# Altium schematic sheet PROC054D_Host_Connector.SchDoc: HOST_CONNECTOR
size 558 x 431 mm; Date: Not shown in title block; ApprovedBy: Not shown in title block; CheckedBy: Not shown in title block; Author: Not shown in title block; CompanyName: Not shown in title block; DrawnBy: a0271760; Engineer: Not shown in title block; Organization: Not shown in title block; Address1: Not shown in title block; Address2: Not shown in title block; Address3: Not shown in title block; Address4: Not shown in title block; DocumentNumber: 9; Revision: Use project pAWRameter SCH_Rev; SheetNumber: 9; SheetTotal: 19; PageSetup: Record=PageOptions¦CenterHorizontal=True¦CenterVertical=True¦PrintScale=1.00¦XCorrection=1.00¦YCorrection=1.00¦PrintKind=0¦BorderSize=5000000¦LeftOffset=0¦BottomOffset=0¦Orientation=2¦PaperLength=1000¦PaperWidth=1000¦Scale=100¦PaperSource=15¦PrintQuality=600¦MediaType=1¦DitherType=10¦PaperKind=Letter¦PrintScaleMode=1
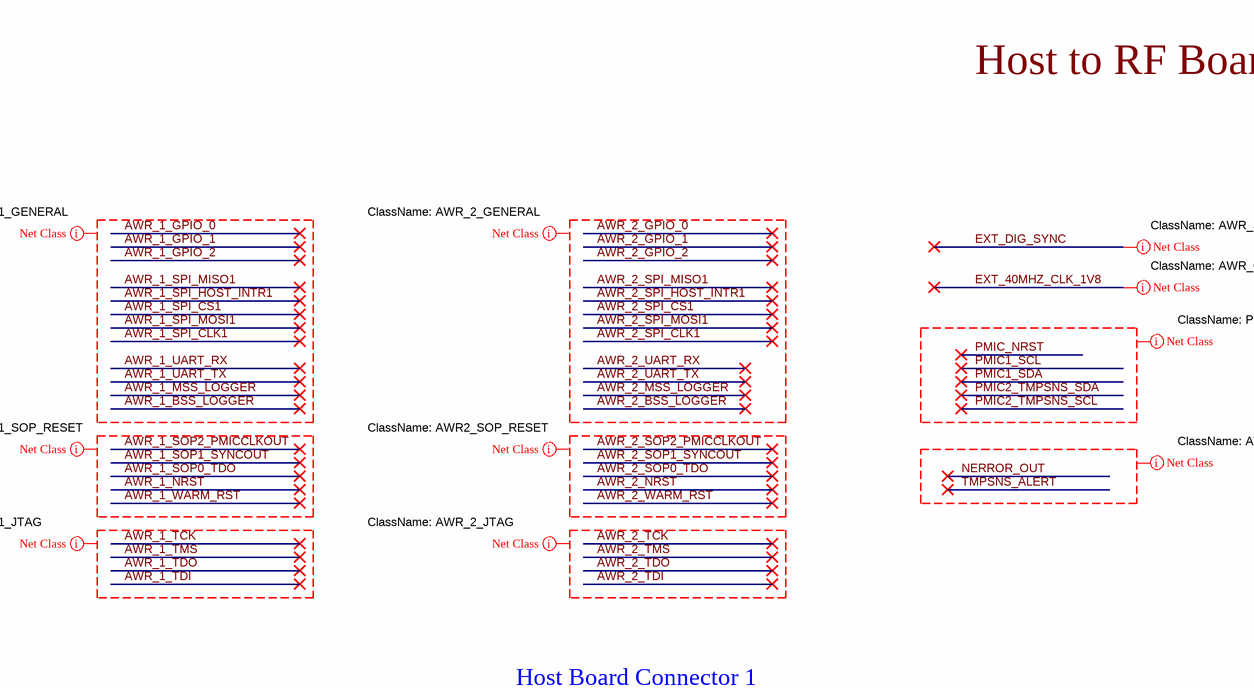
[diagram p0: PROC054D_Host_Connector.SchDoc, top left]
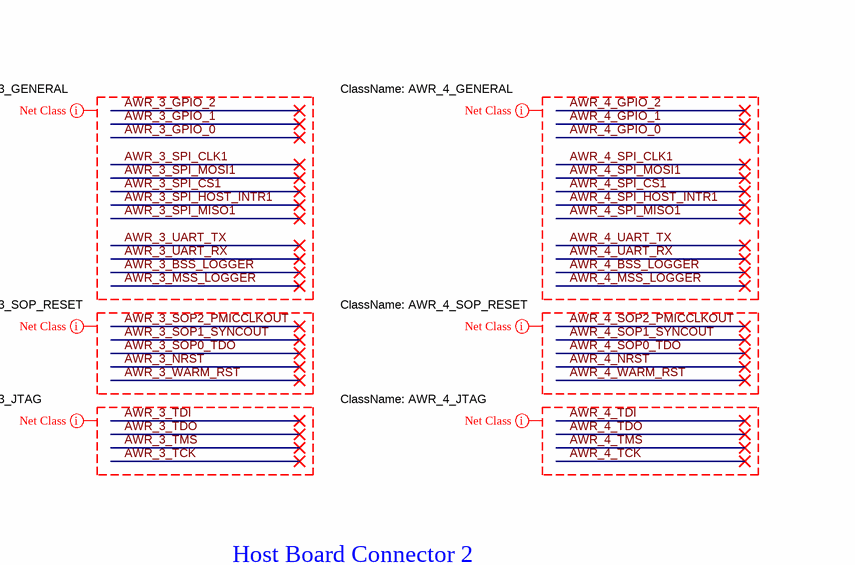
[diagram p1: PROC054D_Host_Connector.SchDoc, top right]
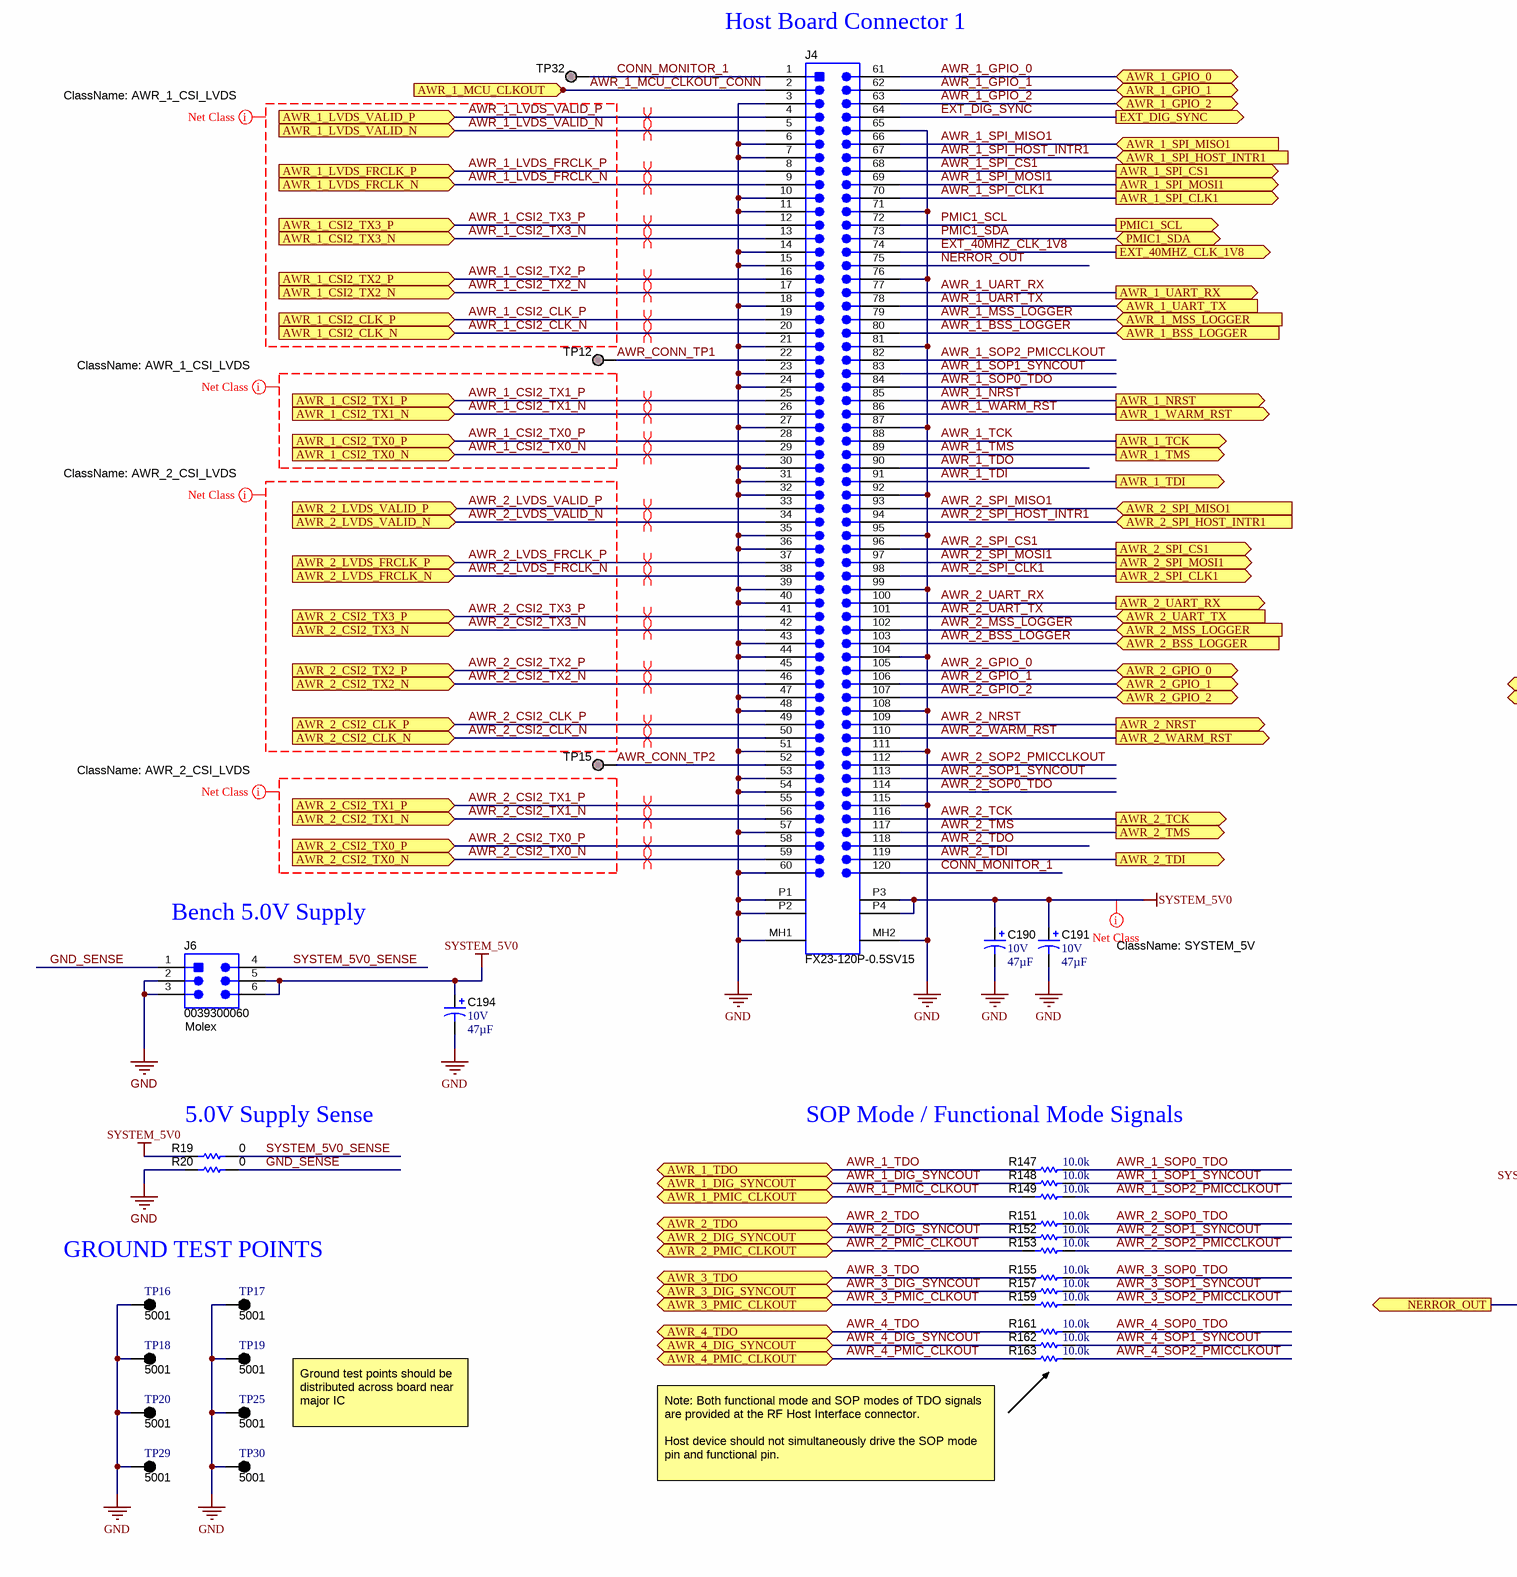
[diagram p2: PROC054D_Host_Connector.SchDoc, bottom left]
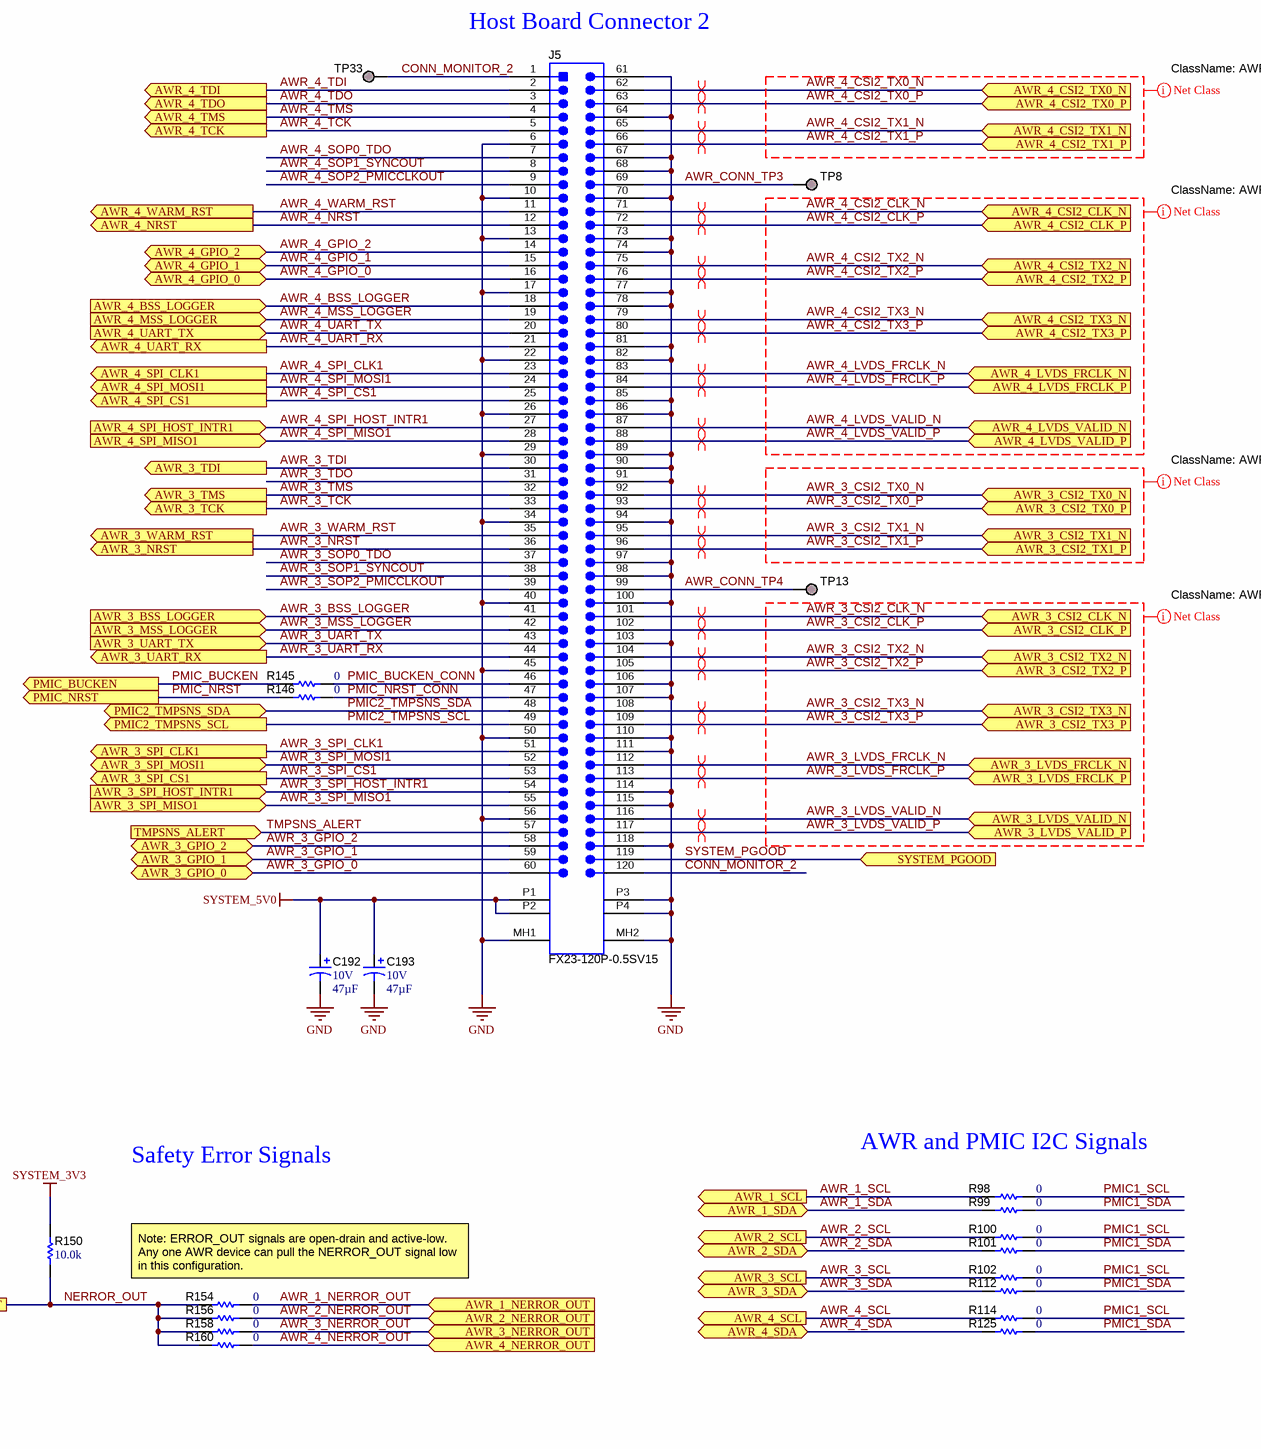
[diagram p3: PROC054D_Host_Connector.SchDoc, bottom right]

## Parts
C190  VDC_V: 10V  ValueDisplayed: 47µF  [3528-21]  (hidden comment: T491B476K010AT)
C191  VDC_V: 10V  ValueDisplayed: 47µF  [3528-21]  (hidden comment: T491B476K010AT)
C192  VDC_V: 10V  ValueDisplayed: 47µF  [3528-21]  (hidden comment: T491B476K010AT)
C193  VDC_V: 10V  ValueDisplayed: 47µF  [3528-21]  (hidden comment: T491B476K010AT)
C194  VDC_V: 10V  ValueDisplayed: 47µF  [3528-21]  (hidden comment: T491B476K010AT)
J4  FX23-120P-0.5SV15  [Hirose_FX23-120P-0_5SV15]
J5  FX23-120P-0.5SV15  [Hirose_FX23-120P-0_5SV15]
J6  0039300060  Manufacturer: Molex  [Molex_0039300060]
R19  ValueDisplayed: 0  [0805L]  (hidden comment: PMR10EZPJ000)
R20  ValueDisplayed: 0  [0805L]  (hidden comment: PMR10EZPJ000)
R98  ValueDisplayed: 0  [0402S]  (hidden comment: CRCW04020000Z0EDHP)
R99  ValueDisplayed: 0  [0402S]  (hidden comment: CRCW04020000Z0EDHP)
R100  ValueDisplayed: 0  [0402S]  (hidden comment: CRCW04020000Z0EDHP)
R101  ValueDisplayed: 0  [0402S]  (hidden comment: CRCW04020000Z0EDHP)
R102  ValueDisplayed: 0  [0402S]  (hidden comment: CRCW04020000Z0EDHP)
R112  ValueDisplayed: 0  [0402S]  (hidden comment: CRCW04020000Z0EDHP)
R114  ValueDisplayed: 0  [0402S]  (hidden comment: CRCW04020000Z0EDHP)
R125  ValueDisplayed: 0  [0402S]  (hidden comment: CRCW04020000Z0EDHP)
R145  ValueDisplayed: 0  [0402]  (hidden comment: ERJ-2GE0R00X)
R146  ValueDisplayed: 0  [0402]  (hidden comment: ERJ-2GE0R00X)
R147  ValueDisplayed: 10.0k  [0402]  (hidden comment: CRCW040210K0FKED)
R148  ValueDisplayed: 10.0k  [0402]  (hidden comment: CRCW040210K0FKED)
R149  ValueDisplayed: 10.0k  [0402]  (hidden comment: CRCW040210K0FKED)
R150  ValueDisplayed: 10.0k  [0402]  (hidden comment: CRCW040210K0FKED)
R151  ValueDisplayed: 10.0k  [0402]  (hidden comment: CRCW040210K0FKED)
R152  ValueDisplayed: 10.0k  [0402]  (hidden comment: CRCW040210K0FKED)
R153  ValueDisplayed: 10.0k  [0402]  (hidden comment: CRCW040210K0FKED)
R154  ValueDisplayed: 0  [0402S]  (hidden comment: CRCW04020000Z0EDHP)
R155  ValueDisplayed: 10.0k  [0402]  (hidden comment: CRCW040210K0FKED)
R156  ValueDisplayed: 0  [0402S]  (hidden comment: CRCW04020000Z0EDHP)
R157  ValueDisplayed: 10.0k  [0402]  (hidden comment: CRCW040210K0FKED)
R158  ValueDisplayed: 0  [0402S]  (hidden comment: CRCW04020000Z0EDHP)
R159  ValueDisplayed: 10.0k  [0402]  (hidden comment: CRCW040210K0FKED)
R160  ValueDisplayed: 0  [0402S]  (hidden comment: CRCW04020000Z0EDHP)
R161  ValueDisplayed: 10.0k  [0402]  (hidden comment: CRCW040210K0FKED)
R162  ValueDisplayed: 10.0k  [0402]  (hidden comment: CRCW040210K0FKED)
R163  ValueDisplayed: 10.0k  [0402]  (hidden comment: CRCW040210K0FKED)
TP8  TP_SM_1MM  [TP_SM_1MM]  (value not drawn)  (no BOM)
TP12  TP_SM_1MM  [TP_SM_1MM]  (value not drawn)  (no BOM)
TP13  TP_SM_1MM  [TP_SM_1MM]  (value not drawn)  (no BOM)
TP15  TP_SM_1MM  [TP_SM_1MM]  (value not drawn)  (no BOM)
TP16  5001  [Keystone5001]
TP17  5001  [Keystone5001]
TP18  5001  [Keystone5001]
TP19  5001  [Keystone5001]
TP20  5001  [Keystone5001]
TP25  5001  [Keystone5001]
TP29  5001  [Keystone5001]
TP30  5001  [Keystone5001]
TP32  TP_SM_1MM  [TP_SM_1MM]  (value not drawn)  (no BOM)
TP33  TP_SM_1MM  [TP_SM_1MM]  (value not drawn)  (no BOM)

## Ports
AWR_1_BSS_LOGGER (in), AWR_1_CSI2_CLK_N (in), AWR_1_CSI2_CLK_P (in), AWR_1_CSI2_TX0_N (in), AWR_1_CSI2_TX0_P (in), AWR_1_CSI2_TX1_N (in), AWR_1_CSI2_TX1_P (in), AWR_1_CSI2_TX2_N (in), AWR_1_CSI2_TX2_P (in), AWR_1_CSI2_TX3_N (in), AWR_1_CSI2_TX3_P (in), AWR_1_DIG_SYNCOUT (bidir), AWR_1_GPIO_0 (bidir), AWR_1_GPIO_1 (bidir), AWR_1_GPIO_2 (bidir), AWR_1_LVDS_FRCLK_N (in), AWR_1_LVDS_FRCLK_P (in), AWR_1_LVDS_VALID_N (in), AWR_1_LVDS_VALID_P (in), AWR_1_MCU_CLKOUT (in), AWR_1_MSS_LOGGER (in), AWR_1_NERROR_OUT (in), AWR_1_NRST (out), AWR_1_PMIC_CLKOUT (bidir), AWR_1_SCL (out), AWR_1_SDA (bidir), AWR_1_SPI_CLK1 (out), AWR_1_SPI_CS1 (out), AWR_1_SPI_HOST_INTR1 (in), AWR_1_SPI_MISO1 (in), AWR_1_SPI_MOSI1 (out), AWR_1_TCK (out), AWR_1_TDI (out), AWR_1_TDO (bidir), AWR_1_TMS (out), AWR_1_UART_RX (out), AWR_1_UART_TX (in), AWR_1_WARM_RST (out), AWR_2_BSS_LOGGER (in), AWR_2_CSI2_CLK_N (in), AWR_2_CSI2_CLK_P (in), AWR_2_CSI2_TX0_N (in), AWR_2_CSI2_TX0_P (in), AWR_2_CSI2_TX1_N (in), AWR_2_CSI2_TX1_P (in), AWR_2_CSI2_TX2_N (in), AWR_2_CSI2_TX2_P (in), AWR_2_CSI2_TX3_N (in), AWR_2_CSI2_TX3_P (in), AWR_2_DIG_SYNCOUT (bidir), AWR_2_GPIO_0 (bidir), AWR_2_GPIO_1 (bidir), AWR_2_GPIO_2 (bidir), AWR_2_LVDS_FRCLK_N (in), AWR_2_LVDS_FRCLK_P (in), AWR_2_LVDS_VALID_N (in), AWR_2_LVDS_VALID_P (in), AWR_2_MSS_LOGGER (in), AWR_2_NERROR_OUT (in), AWR_2_NRST (out), AWR_2_PMIC_CLKOUT (bidir), AWR_2_SCL (out), AWR_2_SDA (bidir), AWR_2_SPI_CLK1 (out), AWR_2_SPI_CS1 (out), AWR_2_SPI_HOST_INTR1 (in), AWR_2_SPI_MISO1 (in), AWR_2_SPI_MOSI1 (out), AWR_2_TCK (out), AWR_2_TDI (out), AWR_2_TDO (bidir), AWR_2_TMS (out), AWR_2_UART_RX (out), AWR_2_UART_TX (in), AWR_2_WARM_RST (out), AWR_3_BSS_LOGGER (in), AWR_3_CSI2_CLK_N (in), AWR_3_CSI2_CLK_P (in), AWR_3_CSI2_TX0_N (in), AWR_3_CSI2_TX0_P (in), AWR_3_CSI2_TX1_N (in), AWR_3_CSI2_TX1_P (in), AWR_3_CSI2_TX2_N (in), AWR_3_CSI2_TX2_P (in), AWR_3_CSI2_TX3_N (in), AWR_3_CSI2_TX3_P (in), AWR_3_DIG_SYNCOUT (bidir), AWR_3_GPIO_0 (bidir), AWR_3_GPIO_1 (bidir), AWR_3_GPIO_2 (bidir), AWR_3_LVDS_FRCLK_N (in), AWR_3_LVDS_FRCLK_P (in), AWR_3_LVDS_VALID_N (in), AWR_3_LVDS_VALID_P (in), AWR_3_MSS_LOGGER (in), AWR_3_NERROR_OUT (in), AWR_3_NRST (out), AWR_3_PMIC_CLKOUT (bidir), AWR_3_SCL (out), AWR_3_SDA (bidir), AWR_3_SPI_CLK1 (out), AWR_3_SPI_CS1 (out), AWR_3_SPI_HOST_INTR1 (in), AWR_3_SPI_MISO1 (in), AWR_3_SPI_MOSI1 (bidir), AWR_3_TCK (out), AWR_3_TDI (out), AWR_3_TDO (bidir), AWR_3_TMS (out), AWR_3_UART_RX (out), AWR_3_UART_TX (in), AWR_3_WARM_RST (out), AWR_4_BSS_LOGGER (in), AWR_4_CSI2_CLK_N (in), AWR_4_CSI2_CLK_P (in), AWR_4_CSI2_TX0_N (in), AWR_4_CSI2_TX0_P (in), AWR_4_CSI2_TX1_N (in), AWR_4_CSI2_TX1_P (in), AWR_4_CSI2_TX2_N (in), AWR_4_CSI2_TX2_P (in), AWR_4_CSI2_TX3_N (in), AWR_4_CSI2_TX3_P (in), AWR_4_DIG_SYNCOUT (bidir), AWR_4_GPIO_0 (bidir), AWR_4_GPIO_1 (bidir), AWR_4_GPIO_2 (bidir), AWR_4_LVDS_FRCLK_N (in), AWR_4_LVDS_FRCLK_P (in), AWR_4_LVDS_VALID_N (in), AWR_4_LVDS_VALID_P (in), AWR_4_MSS_LOGGER (in), AWR_4_NERROR_OUT (in), AWR_4_NRST (out), AWR_4_PMIC_CLKOUT (bidir), AWR_4_SCL (out), AWR_4_SDA (bidir), AWR_4_SPI_CLK1 (out), AWR_4_SPI_CS1 (out), AWR_4_SPI_HOST_INTR1 (in), AWR_4_SPI_MISO1 (in), AWR_4_SPI_MOSI1 (out), AWR_4_TCK (out), AWR_4_TDI (out), AWR_4_TDO (bidir), AWR_4_TDO (out), AWR_4_TMS (out), AWR_4_UART_RX (out), AWR_4_UART_TX (in), AWR_4_WARM_RST (out), EXT_40MHZ_CLK_1V8 (out), EXT_DIG_SYNC (out), NERROR_OUT (out), PMIC1_SCL (out), PMIC1_SDA (bidir), PMIC2_TMPSNS_SCL (out), PMIC2_TMPSNS_SDA (bidir), PMIC_BUCKEN (out), PMIC_NRST (out), SYSTEM_PGOOD (in), TMPSNS_ALERT (in)

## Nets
GND: C190.2(-) C191.2(-) C192.2(-) C193.2(-) C194.2(-) J4.3 J4.6 J4.7 J4.10 J4.11 J4.14 J4.15 J4.18 J4.21 J4.23 J4.24 J4.27 J4.30 J4.31 J4.32 J4.35 J4.36 J4.39 J4.40 J4.43 J4.44 J4.47 J4.48 J4.51 J4.53 J4.54 J4.57 J4.60 J4.65 J4.71 J4.76 J4.81 J4.87 J4.92 J4.95 J4.99 J4.104 J4.108 J4.111 J4.115 J4.MH1 J4.MH2 J4.P1 J4.P2 J5.6 J5.10 J5.13 J5.17 J5.22 J5.26 J5.29 J5.34 J5.40 J5.45 J5.50 J5.56 J5.61 J5.64 J5.67 J5.68 J5.70 J5.73 J5.74 J5.77 J5.78 J5.81 J5.82 J5.85 J5.86 J5.89 J5.90 J5.91 J5.94 J5.97 J5.98 J5.100 J5.103 J5.106 J5.107 J5.110 J5.111 J5.114 J5.115 J5.118 J5.MH1 J5.MH2 J5.P3 J5.P4 J6.2 J6.3 R20.1 TP16.1 TP17.1 TP18.1 TP19.1 TP20.1 TP25.1 TP29.1 TP30.1
SYSTEM_3V3: R150.2
SYSTEM_5V0: C190.1(+) C191.1(+) C192.1(+) C193.1(+) C194.1(+) J4.P3 J4.P4 J5.P1 J5.P2 J6.5 J6.6 R19.1
AWR_1_BSS_LOGGER: J4.80 ; port AWR_1_BSS_LOGGER
AWR_1_CSI2_CLK_N: J4.20 ; port AWR_1_CSI2_CLK_N
AWR_1_CSI2_CLK_P: J4.19 ; port AWR_1_CSI2_CLK_P
AWR_1_CSI2_TX0_N: J4.29 ; port AWR_1_CSI2_TX0_N
AWR_1_CSI2_TX0_P: J4.28 ; port AWR_1_CSI2_TX0_P
AWR_1_CSI2_TX1_N: J4.26 ; port AWR_1_CSI2_TX1_N
AWR_1_CSI2_TX1_P: J4.25 ; port AWR_1_CSI2_TX1_P
AWR_1_CSI2_TX2_N: J4.17 ; port AWR_1_CSI2_TX2_N
AWR_1_CSI2_TX2_P: J4.16 ; port AWR_1_CSI2_TX2_P
AWR_1_CSI2_TX3_N: J4.13 ; port AWR_1_CSI2_TX3_N
AWR_1_CSI2_TX3_P: J4.12 ; port AWR_1_CSI2_TX3_P
AWR_1_DIG_SYNCOUT: R148.1 ; port AWR_1_DIG_SYNCOUT
AWR_1_GPIO_0: J4.61 ; port AWR_1_GPIO_0
AWR_1_GPIO_1: J4.62 ; port AWR_1_GPIO_1
AWR_1_GPIO_2: J4.63 ; port AWR_1_GPIO_2
AWR_1_LVDS_FRCLK_N: J4.9 ; port AWR_1_LVDS_FRCLK_N
AWR_1_LVDS_FRCLK_P: J4.8 ; port AWR_1_LVDS_FRCLK_P
AWR_1_LVDS_VALID_N: J4.5 ; port AWR_1_LVDS_VALID_N
AWR_1_LVDS_VALID_P: J4.4 ; port AWR_1_LVDS_VALID_P
AWR_1_MCU_CLKOUT_CONN: J4.2 ; port AWR_1_MCU_CLKOUT
AWR_1_MSS_LOGGER: J4.79 ; port AWR_1_MSS_LOGGER
AWR_1_NERROR_OUT: R154.1 ; port AWR_1_NERROR_OUT
AWR_1_NRST: J4.85 ; port AWR_1_NRST
AWR_1_PMIC_CLKOUT: R149.1 ; port AWR_1_PMIC_CLKOUT
AWR_1_SCL: R98.2 ; port AWR_1_SCL
AWR_1_SDA: R99.2 ; port AWR_1_SDA
AWR_1_SOP0_TDO: J4.84 R147.2
AWR_1_SOP1_SYNCOUT: J4.83 R148.2
AWR_1_SOP2_PMICCLKOUT: J4.82 R149.2
AWR_1_SPI_CLK1: J4.70 ; port AWR_1_SPI_CLK1
AWR_1_SPI_CS1: J4.68 ; port AWR_1_SPI_CS1
AWR_1_SPI_HOST_INTR1: J4.67 ; port AWR_1_SPI_HOST_INTR1
AWR_1_SPI_MISO1: J4.66 ; port AWR_1_SPI_MISO1
AWR_1_SPI_MOSI1: J4.69 ; port AWR_1_SPI_MOSI1
AWR_1_TCK: J4.88 ; port AWR_1_TCK
AWR_1_TDI: J4.91 ; port AWR_1_TDI
AWR_1_TDO: J4.90 R147.1 ; port AWR_1_TDO
AWR_1_TMS: J4.89 ; port AWR_1_TMS
AWR_1_UART_RX: J4.77 ; port AWR_1_UART_RX
AWR_1_UART_TX: J4.78 ; port AWR_1_UART_TX
AWR_1_WARM_RST: J4.86 ; port AWR_1_WARM_RST
AWR_2_BSS_LOGGER: J4.103 ; port AWR_2_BSS_LOGGER
AWR_2_CSI2_CLK_N: J4.50 ; port AWR_2_CSI2_CLK_N
AWR_2_CSI2_CLK_P: J4.49 ; port AWR_2_CSI2_CLK_P
AWR_2_CSI2_TX0_N: J4.59 ; port AWR_2_CSI2_TX0_N
AWR_2_CSI2_TX0_P: J4.58 ; port AWR_2_CSI2_TX0_P
AWR_2_CSI2_TX1_N: J4.56 ; port AWR_2_CSI2_TX1_N
AWR_2_CSI2_TX1_P: J4.55 ; port AWR_2_CSI2_TX1_P
AWR_2_CSI2_TX2_N: J4.46 ; port AWR_2_CSI2_TX2_N
AWR_2_CSI2_TX2_P: J4.45 ; port AWR_2_CSI2_TX2_P
AWR_2_CSI2_TX3_N: J4.42 ; port AWR_2_CSI2_TX3_N
AWR_2_CSI2_TX3_P: J4.41 ; port AWR_2_CSI2_TX3_P
AWR_2_DIG_SYNCOUT: R152.1 ; port AWR_2_DIG_SYNCOUT
AWR_2_GPIO_0: J4.105 ; port AWR_2_GPIO_0
AWR_2_GPIO_1: J4.106 ; port AWR_2_GPIO_1
AWR_2_GPIO_2: J4.107 ; port AWR_2_GPIO_2
AWR_2_LVDS_FRCLK_N: J4.38 ; port AWR_2_LVDS_FRCLK_N
AWR_2_LVDS_FRCLK_P: J4.37 ; port AWR_2_LVDS_FRCLK_P
AWR_2_LVDS_VALID_N: J4.34 ; port AWR_2_LVDS_VALID_N
AWR_2_LVDS_VALID_P: J4.33 ; port AWR_2_LVDS_VALID_P
AWR_2_MSS_LOGGER: J4.102 ; port AWR_2_MSS_LOGGER
AWR_2_NERROR_OUT: R156.1 ; port AWR_2_NERROR_OUT
AWR_2_NRST: J4.109 ; port AWR_2_NRST
AWR_2_PMIC_CLKOUT: R153.1 ; port AWR_2_PMIC_CLKOUT
AWR_2_SCL: R100.2 ; port AWR_2_SCL
AWR_2_SDA: R101.2 ; port AWR_2_SDA
AWR_2_SOP0_TDO: J4.114 R151.2
AWR_2_SOP1_SYNCOUT: J4.113 R152.2
AWR_2_SOP2_PMICCLKOUT: J4.112 R153.2
AWR_2_SPI_CLK1: J4.98 ; port AWR_2_SPI_CLK1
AWR_2_SPI_CS1: J4.96 ; port AWR_2_SPI_CS1
AWR_2_SPI_HOST_INTR1: J4.94 ; port AWR_2_SPI_HOST_INTR1
AWR_2_SPI_MISO1: J4.93 ; port AWR_2_SPI_MISO1
AWR_2_SPI_MOSI1: J4.97 ; port AWR_2_SPI_MOSI1
AWR_2_TCK: J4.116 ; port AWR_2_TCK
AWR_2_TDI: J4.119 ; port AWR_2_TDI
AWR_2_TDO: J4.118 R151.1 ; port AWR_2_TDO
AWR_2_TMS: J4.117 ; port AWR_2_TMS
AWR_2_UART_RX: J4.100 ; port AWR_2_UART_RX
AWR_2_UART_TX: J4.101 ; port AWR_2_UART_TX
AWR_2_WARM_RST: J4.110 ; port AWR_2_WARM_RST
AWR_3_BSS_LOGGER: J5.41 ; port AWR_3_BSS_LOGGER
AWR_3_CSI2_CLK_N: J5.101 ; port AWR_3_CSI2_CLK_N
AWR_3_CSI2_CLK_P: J5.102 ; port AWR_3_CSI2_CLK_P
AWR_3_CSI2_TX0_N: J5.92 ; port AWR_3_CSI2_TX0_N
AWR_3_CSI2_TX0_P: J5.93 ; port AWR_3_CSI2_TX0_P
AWR_3_CSI2_TX1_N: J5.95 ; port AWR_3_CSI2_TX1_N
AWR_3_CSI2_TX1_P: J5.96 ; port AWR_3_CSI2_TX1_P
AWR_3_CSI2_TX2_N: J5.104 ; port AWR_3_CSI2_TX2_N
AWR_3_CSI2_TX2_P: J5.105 ; port AWR_3_CSI2_TX2_P
AWR_3_CSI2_TX3_N: J5.108 ; port AWR_3_CSI2_TX3_N
AWR_3_CSI2_TX3_P: J5.109 ; port AWR_3_CSI2_TX3_P
AWR_3_DIG_SYNCOUT: R157.1 ; port AWR_3_DIG_SYNCOUT
AWR_3_GPIO_0: J5.60 ; port AWR_3_GPIO_0
AWR_3_GPIO_1: J5.59 ; port AWR_3_GPIO_1
AWR_3_GPIO_2: J5.58 ; port AWR_3_GPIO_2
AWR_3_LVDS_FRCLK_N: J5.112 ; port AWR_3_LVDS_FRCLK_N
AWR_3_LVDS_FRCLK_P: J5.113 ; port AWR_3_LVDS_FRCLK_P
AWR_3_LVDS_VALID_N: J5.116 ; port AWR_3_LVDS_VALID_N
AWR_3_LVDS_VALID_P: J5.117 ; port AWR_3_LVDS_VALID_P
AWR_3_MSS_LOGGER: J5.42 ; port AWR_3_MSS_LOGGER
AWR_3_NERROR_OUT: R158.1 ; port AWR_3_NERROR_OUT
AWR_3_NRST: J5.36 ; port AWR_3_NRST
AWR_3_PMIC_CLKOUT: R159.1 ; port AWR_3_PMIC_CLKOUT
AWR_3_SCL: R102.2 ; port AWR_3_SCL
AWR_3_SDA: R112.2 ; port AWR_3_SDA
AWR_3_SOP0_TDO: J5.37 R155.2
AWR_3_SOP1_SYNCOUT: J5.38 R157.2
AWR_3_SOP2_PMICCLKOUT: J5.39 R159.2
AWR_3_SPI_CLK1: J5.51 ; port AWR_3_SPI_CLK1
AWR_3_SPI_CS1: J5.53 ; port AWR_3_SPI_CS1
AWR_3_SPI_HOST_INTR1: J5.54 ; port AWR_3_SPI_HOST_INTR1
AWR_3_SPI_MISO1: J5.55 ; port AWR_3_SPI_MISO1
AWR_3_SPI_MOSI1: J5.52 ; port AWR_3_SPI_MOSI1
AWR_3_TCK: J5.33 ; port AWR_3_TCK
AWR_3_TDI: J5.30 ; port AWR_3_TDI
AWR_3_TDO: J5.31 R155.1 ; port AWR_3_TDO
AWR_3_TMS: J5.32 ; port AWR_3_TMS
AWR_3_UART_RX: J5.44 ; port AWR_3_UART_RX
AWR_3_UART_TX: J5.43 ; port AWR_3_UART_TX
AWR_3_WARM_RST: J5.35 ; port AWR_3_WARM_RST
AWR_4_BSS_LOGGER: J5.18 ; port AWR_4_BSS_LOGGER
AWR_4_CSI2_CLK_N: J5.71 ; port AWR_4_CSI2_CLK_N
AWR_4_CSI2_CLK_P: J5.72 ; port AWR_4_CSI2_CLK_P
AWR_4_CSI2_TX0_N: J5.62 ; port AWR_4_CSI2_TX0_N
AWR_4_CSI2_TX0_P: J5.63 ; port AWR_4_CSI2_TX0_P
AWR_4_CSI2_TX1_N: J5.65 ; port AWR_4_CSI2_TX1_N
AWR_4_CSI2_TX1_P: J5.66 ; port AWR_4_CSI2_TX1_P
AWR_4_CSI2_TX2_N: J5.75 ; port AWR_4_CSI2_TX2_N
AWR_4_CSI2_TX2_P: J5.76 ; port AWR_4_CSI2_TX2_P
AWR_4_CSI2_TX3_N: J5.79 ; port AWR_4_CSI2_TX3_N
AWR_4_CSI2_TX3_P: J5.80 ; port AWR_4_CSI2_TX3_P
AWR_4_DIG_SYNCOUT: R162.1 ; port AWR_4_DIG_SYNCOUT
AWR_4_GPIO_0: J5.16 ; port AWR_4_GPIO_0
AWR_4_GPIO_1: J5.15 ; port AWR_4_GPIO_1
AWR_4_GPIO_2: J5.14 ; port AWR_4_GPIO_2
AWR_4_LVDS_FRCLK_N: J5.83 ; port AWR_4_LVDS_FRCLK_N
AWR_4_LVDS_FRCLK_P: J5.84 ; port AWR_4_LVDS_FRCLK_P
AWR_4_LVDS_VALID_N: J5.87 ; port AWR_4_LVDS_VALID_N
AWR_4_LVDS_VALID_P: J5.88 ; port AWR_4_LVDS_VALID_P
AWR_4_MSS_LOGGER: J5.19 ; port AWR_4_MSS_LOGGER
AWR_4_NERROR_OUT: R160.1 ; port AWR_4_NERROR_OUT
AWR_4_NRST: J5.12 ; port AWR_4_NRST
AWR_4_PMIC_CLKOUT: R163.1 ; port AWR_4_PMIC_CLKOUT
AWR_4_SCL: R114.2 ; port AWR_4_SCL
AWR_4_SDA: R125.2 ; port AWR_4_SDA
AWR_4_SOP0_TDO: J5.7 R161.2
AWR_4_SOP1_SYNCOUT: J5.8 R162.2
AWR_4_SOP2_PMICCLKOUT: J5.9 R163.2
AWR_4_SPI_CLK1: J5.23 ; port AWR_4_SPI_CLK1
AWR_4_SPI_CS1: J5.25 ; port AWR_4_SPI_CS1
AWR_4_SPI_HOST_INTR1: J5.27 ; port AWR_4_SPI_HOST_INTR1
AWR_4_SPI_MISO1: J5.28 ; port AWR_4_SPI_MISO1
AWR_4_SPI_MOSI1: J5.24 ; port AWR_4_SPI_MOSI1
AWR_4_TCK: J5.5 ; port AWR_4_TCK
AWR_4_TDI: J5.2 ; port AWR_4_TDI
AWR_4_TDO: J5.3 R161.1 ; port AWR_4_TDO
AWR_4_TMS: J5.4 ; port AWR_4_TMS
AWR_4_UART_RX: J5.21 ; port AWR_4_UART_RX
AWR_4_UART_TX: J5.20 ; port AWR_4_UART_TX
AWR_4_WARM_RST: J5.11 ; port AWR_4_WARM_RST
AWR_CONN_TP1: J4.22 TP12.1
AWR_CONN_TP2: J4.52 TP15.1
AWR_CONN_TP3: J5.69 TP8.1
AWR_CONN_TP4: J5.99 TP13.1
CONN_MONITOR_1: J4.1 J4.120 TP32.1
CONN_MONITOR_2: J5.1 J5.120 TP33.1
EXT_40MHZ_CLK_1V8: J4.74 ; port EXT_40MHZ_CLK_1V8
EXT_DIG_SYNC: J4.64 ; port EXT_DIG_SYNC
GND_SENSE: J6.1 R20.2
NERROR_OUT: J4.75 R150.1 R154.2 R156.2 R158.2 R160.2 ; port NERROR_OUT
PMIC1_SCL: J4.72 R98.1 R100.1 R102.1 R114.1 ; port PMIC1_SCL
PMIC1_SDA: J4.73 R99.1 R101.1 R112.1 R125.1 ; port PMIC1_SDA
PMIC2_TMPSNS_SCL: J5.49 ; port PMIC2_TMPSNS_SCL
PMIC2_TMPSNS_SDA: J5.48 ; port PMIC2_TMPSNS_SDA
PMIC_BUCKEN: R145.1 ; port PMIC_BUCKEN
PMIC_BUCKEN_CONN: J5.46 R145.2
PMIC_NRST: R146.1 ; port PMIC_NRST
PMIC_NRST_CONN: J5.47 R146.2
SYSTEM_5V0_SENSE: J6.4 R19.2
SYSTEM_PGOOD: J5.119 ; port SYSTEM_PGOOD
TMPSNS_ALERT: J5.57 ; port TMPSNS_ALERT

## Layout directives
net class AWR_1_CSI_LVDS: AWR_1_CSI2_CLK_N, AWR_1_CSI2_CLK_P, AWR_1_CSI2_TX0_N, AWR_1_CSI2_TX0_P, AWR_1_CSI2_TX1_N, AWR_1_CSI2_TX1_P, AWR_1_CSI2_TX2_N, AWR_1_CSI2_TX2_P, AWR_1_CSI2_TX3_N, AWR_1_CSI2_TX3_P, AWR_1_LVDS_FRCLK_N, AWR_1_LVDS_FRCLK_P, AWR_1_LVDS_VALID_N, AWR_1_LVDS_VALID_P
net class AWR_2_CSI_LVDS: AWR_2_CSI2_CLK_N, AWR_2_CSI2_CLK_P, AWR_2_CSI2_TX0_N, AWR_2_CSI2_TX0_P, AWR_2_CSI2_TX1_N, AWR_2_CSI2_TX1_P, AWR_2_CSI2_TX2_N, AWR_2_CSI2_TX2_P, AWR_2_CSI2_TX3_N, AWR_2_CSI2_TX3_P, AWR_2_LVDS_FRCLK_N, AWR_2_LVDS_FRCLK_P, AWR_2_LVDS_VALID_N, AWR_2_LVDS_VALID_P
net class AWR_1_GENERAL: AWR_1_BSS_LOGGER, AWR_1_GPIO_0, AWR_1_GPIO_1, AWR_1_GPIO_2, AWR_1_MSS_LOGGER, AWR_1_SPI_CLK1, AWR_1_SPI_CS1, AWR_1_SPI_HOST_INTR1, AWR_1_SPI_MISO1, AWR_1_SPI_MOSI1, AWR_1_UART_RX, AWR_1_UART_TX
net class AWR_1_SOP_RESET: AWR_1_NRST, AWR_1_SOP0_TDO, AWR_1_SOP1_SYNCOUT, AWR_1_SOP2_PMICCLKOUT, AWR_1_WARM_RST
net class AWR_1_JTAG: AWR_1_TCK, AWR_1_TDI, AWR_1_TDO, AWR_1_TMS
net class AWR_SYNC: EXT_DIG_SYNC
net class PMIC_CONTROL: PMIC1_SCL, PMIC1_SDA, PMIC2_TMPSNS_SCL, PMIC2_TMPSNS_SDA, PMIC_NRST
net class AWR_SAFETY: NERROR_OUT, TMPSNS_ALERT
net class AWR_2_JTAG: AWR_2_TCK, AWR_2_TDI, AWR_2_TDO, AWR_2_TMS
net class AWR2_SOP_RESET: AWR_2_NRST, AWR_2_SOP0_TDO, AWR_2_SOP1_SYNCOUT, AWR_2_SOP2_PMICCLKOUT, AWR_2_WARM_RST
net class AWR_2_GENERAL: AWR_2_BSS_LOGGER, AWR_2_GPIO_0, AWR_2_GPIO_1, AWR_2_GPIO_2, AWR_2_MSS_LOGGER, AWR_2_SPI_CLK1, AWR_2_SPI_CS1, AWR_2_SPI_HOST_INTR1, AWR_2_SPI_MISO1, AWR_2_SPI_MOSI1, AWR_2_UART_RX, AWR_2_UART_TX
differential pair: AWR_1_CSI2_CLK_N, AWR_1_CSI2_CLK_P, AWR_1_CSI2_TX0_N, AWR_1_CSI2_TX0_P, AWR_1_CSI2_TX1_N, AWR_1_CSI2_TX1_P, AWR_1_CSI2_TX2_N, AWR_1_CSI2_TX2_P, AWR_1_CSI2_TX3_N, AWR_1_CSI2_TX3_P, AWR_1_LVDS_FRCLK_N, AWR_1_LVDS_FRCLK_P, AWR_1_LVDS_VALID_N, AWR_1_LVDS_VALID_P, AWR_2_CSI2_CLK_N, AWR_2_CSI2_CLK_P, AWR_2_CSI2_TX0_N, AWR_2_CSI2_TX0_P, AWR_2_CSI2_TX1_N, AWR_2_CSI2_TX1_P, AWR_2_CSI2_TX2_N, AWR_2_CSI2_TX2_P, AWR_2_CSI2_TX3_N, AWR_2_CSI2_TX3_P, AWR_2_LVDS_FRCLK_N, AWR_2_LVDS_FRCLK_P, AWR_2_LVDS_VALID_N, AWR_2_LVDS_VALID_P, AWR_3_CSI2_CLK_N, AWR_3_CSI2_CLK_P, AWR_3_CSI2_TX0_N, AWR_3_CSI2_TX0_P, AWR_3_CSI2_TX1_N, AWR_3_CSI2_TX1_P, AWR_3_CSI2_TX2_N, AWR_3_CSI2_TX2_P, AWR_3_CSI2_TX3_N, AWR_3_CSI2_TX3_P, AWR_3_LVDS_FRCLK_N, AWR_3_LVDS_FRCLK_P, AWR_3_LVDS_VALID_N, AWR_3_LVDS_VALID_P, AWR_4_CSI2_CLK_N, AWR_4_CSI2_CLK_P, AWR_4_CSI2_TX0_N, AWR_4_CSI2_TX0_P, AWR_4_CSI2_TX1_N, AWR_4_CSI2_TX1_P, AWR_4_CSI2_TX2_N, AWR_4_CSI2_TX2_P, AWR_4_CSI2_TX3_N, AWR_4_CSI2_TX3_P, AWR_4_LVDS_FRCLK_N, AWR_4_LVDS_FRCLK_P, AWR_4_LVDS_VALID_N, AWR_4_LVDS_VALID_P
net class AWR_4_CSI_LVDS: AWR_4_CSI2_CLK_N, AWR_4_CSI2_CLK_P, AWR_4_CSI2_TX0_N, AWR_4_CSI2_TX0_P, AWR_4_CSI2_TX1_N, AWR_4_CSI2_TX1_P, AWR_4_CSI2_TX2_N, AWR_4_CSI2_TX2_P, AWR_4_CSI2_TX3_N, AWR_4_CSI2_TX3_P, AWR_4_LVDS_FRCLK_N, AWR_4_LVDS_FRCLK_P, AWR_4_LVDS_VALID_N, AWR_4_LVDS_VALID_P
net class AWR_3_CSI_LVDS: AWR_3_CSI2_CLK_N, AWR_3_CSI2_CLK_P, AWR_3_CSI2_TX0_N, AWR_3_CSI2_TX0_P, AWR_3_CSI2_TX1_N, AWR_3_CSI2_TX1_P, AWR_3_CSI2_TX2_N, AWR_3_CSI2_TX2_P, AWR_3_CSI2_TX3_N, AWR_3_CSI2_TX3_P, AWR_3_LVDS_FRCLK_N, AWR_3_LVDS_FRCLK_P, AWR_3_LVDS_VALID_N, AWR_3_LVDS_VALID_P
net class AWR_3_JTAG: AWR_3_TCK, AWR_3_TDI, AWR_3_TDO, AWR_3_TMS
net class AWR_3_SOP_RESET: AWR_3_NRST, AWR_3_SOP0_TDO, AWR_3_SOP1_SYNCOUT, AWR_3_SOP2_PMICCLKOUT, AWR_3_WARM_RST
net class AWR_3_GENERAL: AWR_3_BSS_LOGGER, AWR_3_GPIO_0, AWR_3_GPIO_1, AWR_3_GPIO_2, AWR_3_MSS_LOGGER, AWR_3_SPI_CLK1, AWR_3_SPI_CS1, AWR_3_SPI_HOST_INTR1, AWR_3_SPI_MISO1, AWR_3_SPI_MOSI1, AWR_3_UART_RX, AWR_3_UART_TX
net class AWR_4_JTAG: AWR_4_TCK, AWR_4_TDI, AWR_4_TDO, AWR_4_TMS
net class AWR_4_SOP_RESET: AWR_4_NRST, AWR_4_SOP0_TDO, AWR_4_SOP1_SYNCOUT, AWR_4_SOP2_PMICCLKOUT, AWR_4_WARM_RST
net class AWR_4_GENERAL: AWR_4_BSS_LOGGER, AWR_4_GPIO_0, AWR_4_GPIO_1, AWR_4_GPIO_2, AWR_4_MSS_LOGGER, AWR_4_SPI_CLK1, AWR_4_SPI_CS1, AWR_4_SPI_HOST_INTR1, AWR_4_SPI_MISO1, AWR_4_SPI_MOSI1, AWR_4_UART_RX, AWR_4_UART_TX
net class AWR_CLOCK: EXT_40MHZ_CLK_1V8
net class SYSTEM_5V: SYSTEM_5V0

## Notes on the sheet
- Host to RF Board Connectors
- (near J4) Host Board Connector 1
- (near J5) Host Board Connector 2
- (near J6) Bench 5.0V Supply
- 5.0V Supply Sense
- SOP Mode / Functional Mode Signals
- Safety Error Signals
- AWR and PMIC I2C Signals
- GROUND TEST POINTS
- Note: ERROR_OUT signals are open-drain and active-low. Any one AWR device can pull the NERROR_OUT signal low in this configuration.
- Ground test points should be distributed across board near major IC
- Note: Both functional mode and SOP modes of TDO signals are provided at the RF Host Interface connector.
  Host device should not simultaneously drive the SOP mode pin and functional pin.

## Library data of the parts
C190-C194 = CMP-0078216-1: CAP, TA, 47 µF, 10 V, +/- 10%, SMD; Manufacturer: Kemet; TaMin_C: -55°C; Polarized: Y; SizeAreaWB_mm2: 17.1; Value: 47uF; TaMax_C: 125°C; SizeZ_mm: 2.1; SizeX_mm: 3.5; SizeY_mm: 2.8; SizeArea_mm2: 9.8; CompType: Capacitor; AEC Qualified: N; AEC Category: Q200
J4 J5 = CMP-0081853-1: Header(shrouded), 0.5mm, 60x2, Gold, SMT; Manufacturer: Hirose Electric Co. Ltd.; Pitch_mm: 0.5; Gender: Male; Cert_UL: Y; Row_Count: 2
J6 = CMP-0082107-1: Header(shrouded), 4.2mm, 3x2, Tin, R/A, TH; Pitch_mm: 4.2; Gender: Male; Cert_CSA: Y; Voltage_V: 600V; Current_A: 13A; Row_Count: 2
R19 R20 = CMP-0081857-1: RES, 0, 0%,  W, AEC-Q200 Grade 0, 0805; Manufacturer: Rohm; SizeAreaWB_mm2: 6.75; SizeArea_mm2: 2.5; AEC Qualified: Y; AEC Category: Q200; Value: 0; SizeZ_mm: 1.45; SizeY_mm: 1.25; CompType: Resistor; SizeX_mm: 2
R98-R102 R112 R114 R125 R154 R156 R158 R160 = CMP-0081856-1: RES, 0, 0%, 0.2 W, AEC-Q200 Grade 0, 0402; Manufacturer: Vishay-Dale; SizeAreaWB_mm2: 3; SizeArea_mm2: 0.5; AEC Qualified: Y; AEC Category: Q200; Value: 0; SizeZ_mm: 0.6; Power_W: 200mW; VDC_V: 50V; Value2: 0.2W; CompType: Resistor; SizeX_mm: 1
R145 R146 = CMP-0026992-3: RES, 0, 5%, 0.1 W, AEC-Q200 Grade 0, 0402; Manufacturer: Panasonic; Power_W: 100mW; TempCo: 600 ppm/C; Value_Code: 0000; Value: 0; EIA_Code: E24; SizeX_mm: 1; SizeY_mm: 0.5; SizeZ_mm: 0.6; Value2: 0.1W; AEC Qualified: Y; VDC_V: 50V; AEC Category: Q200; SizeAreaWB_mm2: 3
R147-R153 R155 R157 R159 R161-R163 = CMP-0025958-3: RES, 10.0 k, 1%, 0.063 W, AEC-Q200 Grade 0, 0402; Manufacturer: Vishay-Dale; Power_W: 63mW; TempCo: 100 ppm/C; Value_Code: 10k0; Value: 10.0k; EIA_Code: E96; Res_ohm: 10k; SizeX_mm: 1; SizeY_mm: 0.5; SizeZ_mm: 0.6; Value2: 0.063W; AEC Qualified: Y; VDC_V: 50V; AEC Category: Q200; AEC Grade: 0
TP8 TP12 TP13 TP15 TP32 TP33 = CMP-0003825-1: 1mm Test Point, SMT; Manufacturer: Any
TP16-TP20 TP25 TP29 TP30 = CMP-0055138-1: Test Point, Miniature, Black, TH; Manufacturer: Keystone; ContactFinish: Silver; Green_Lifecycle: Active; Green_REACh: Passed; CNHeader: FALSE; CT: TRUE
